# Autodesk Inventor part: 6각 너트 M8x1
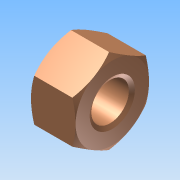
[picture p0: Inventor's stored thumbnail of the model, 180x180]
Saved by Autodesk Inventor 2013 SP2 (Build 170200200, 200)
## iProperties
Created: 2025-10
Part Number: 6각 너트 M8x1
Material: Generic
Document SubType Name: Modeling
Designer: 601
Density: 1 g/cm^3
변환 표준: STEP AP214IS
전처리기: Build: 200, Release: 2013 SP2 Update 6 - Date: Thu 07/17/2014
전송 단위: 밀리미터
불확실성: 0.01
Author: 601
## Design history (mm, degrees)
node "6각 너트 M8x11"
body "Solid1"
node "기준1"
